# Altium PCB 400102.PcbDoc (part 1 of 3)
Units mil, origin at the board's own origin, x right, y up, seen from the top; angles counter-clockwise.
Board outline 3703.69 x 2381.89 mil, 2 copper layers (Top Layer, Bottom Layer), stack 61.8 mil thick; 220 components, 149 nets, 880 pads, 750 vias.
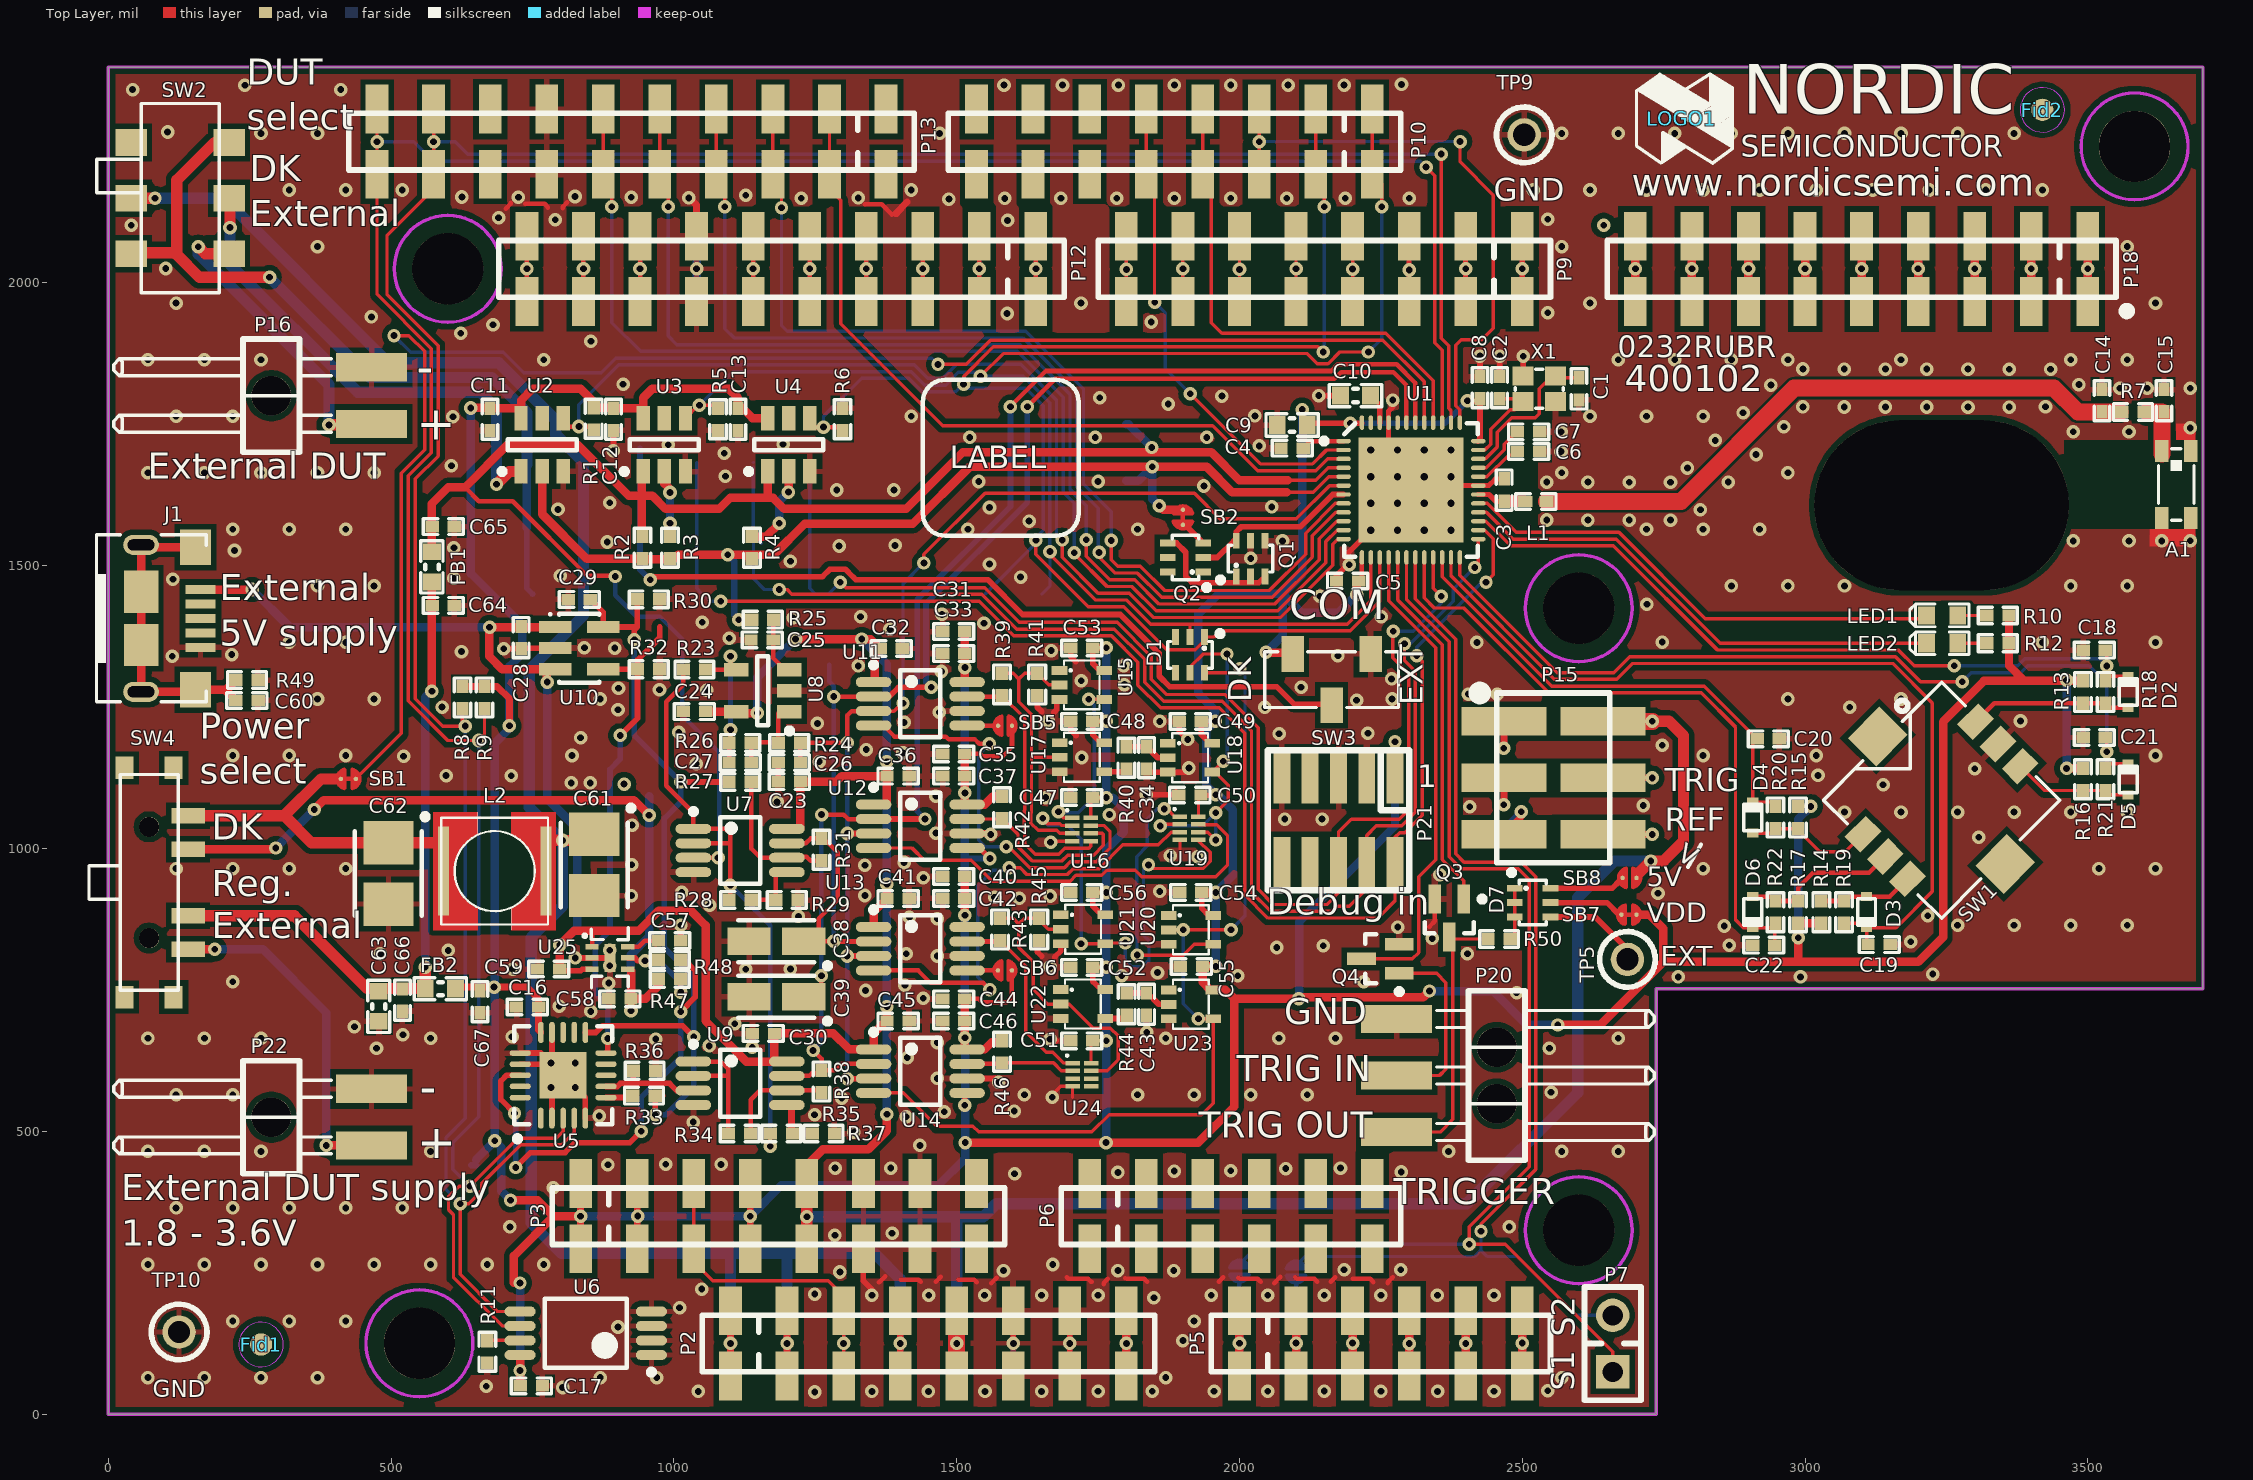
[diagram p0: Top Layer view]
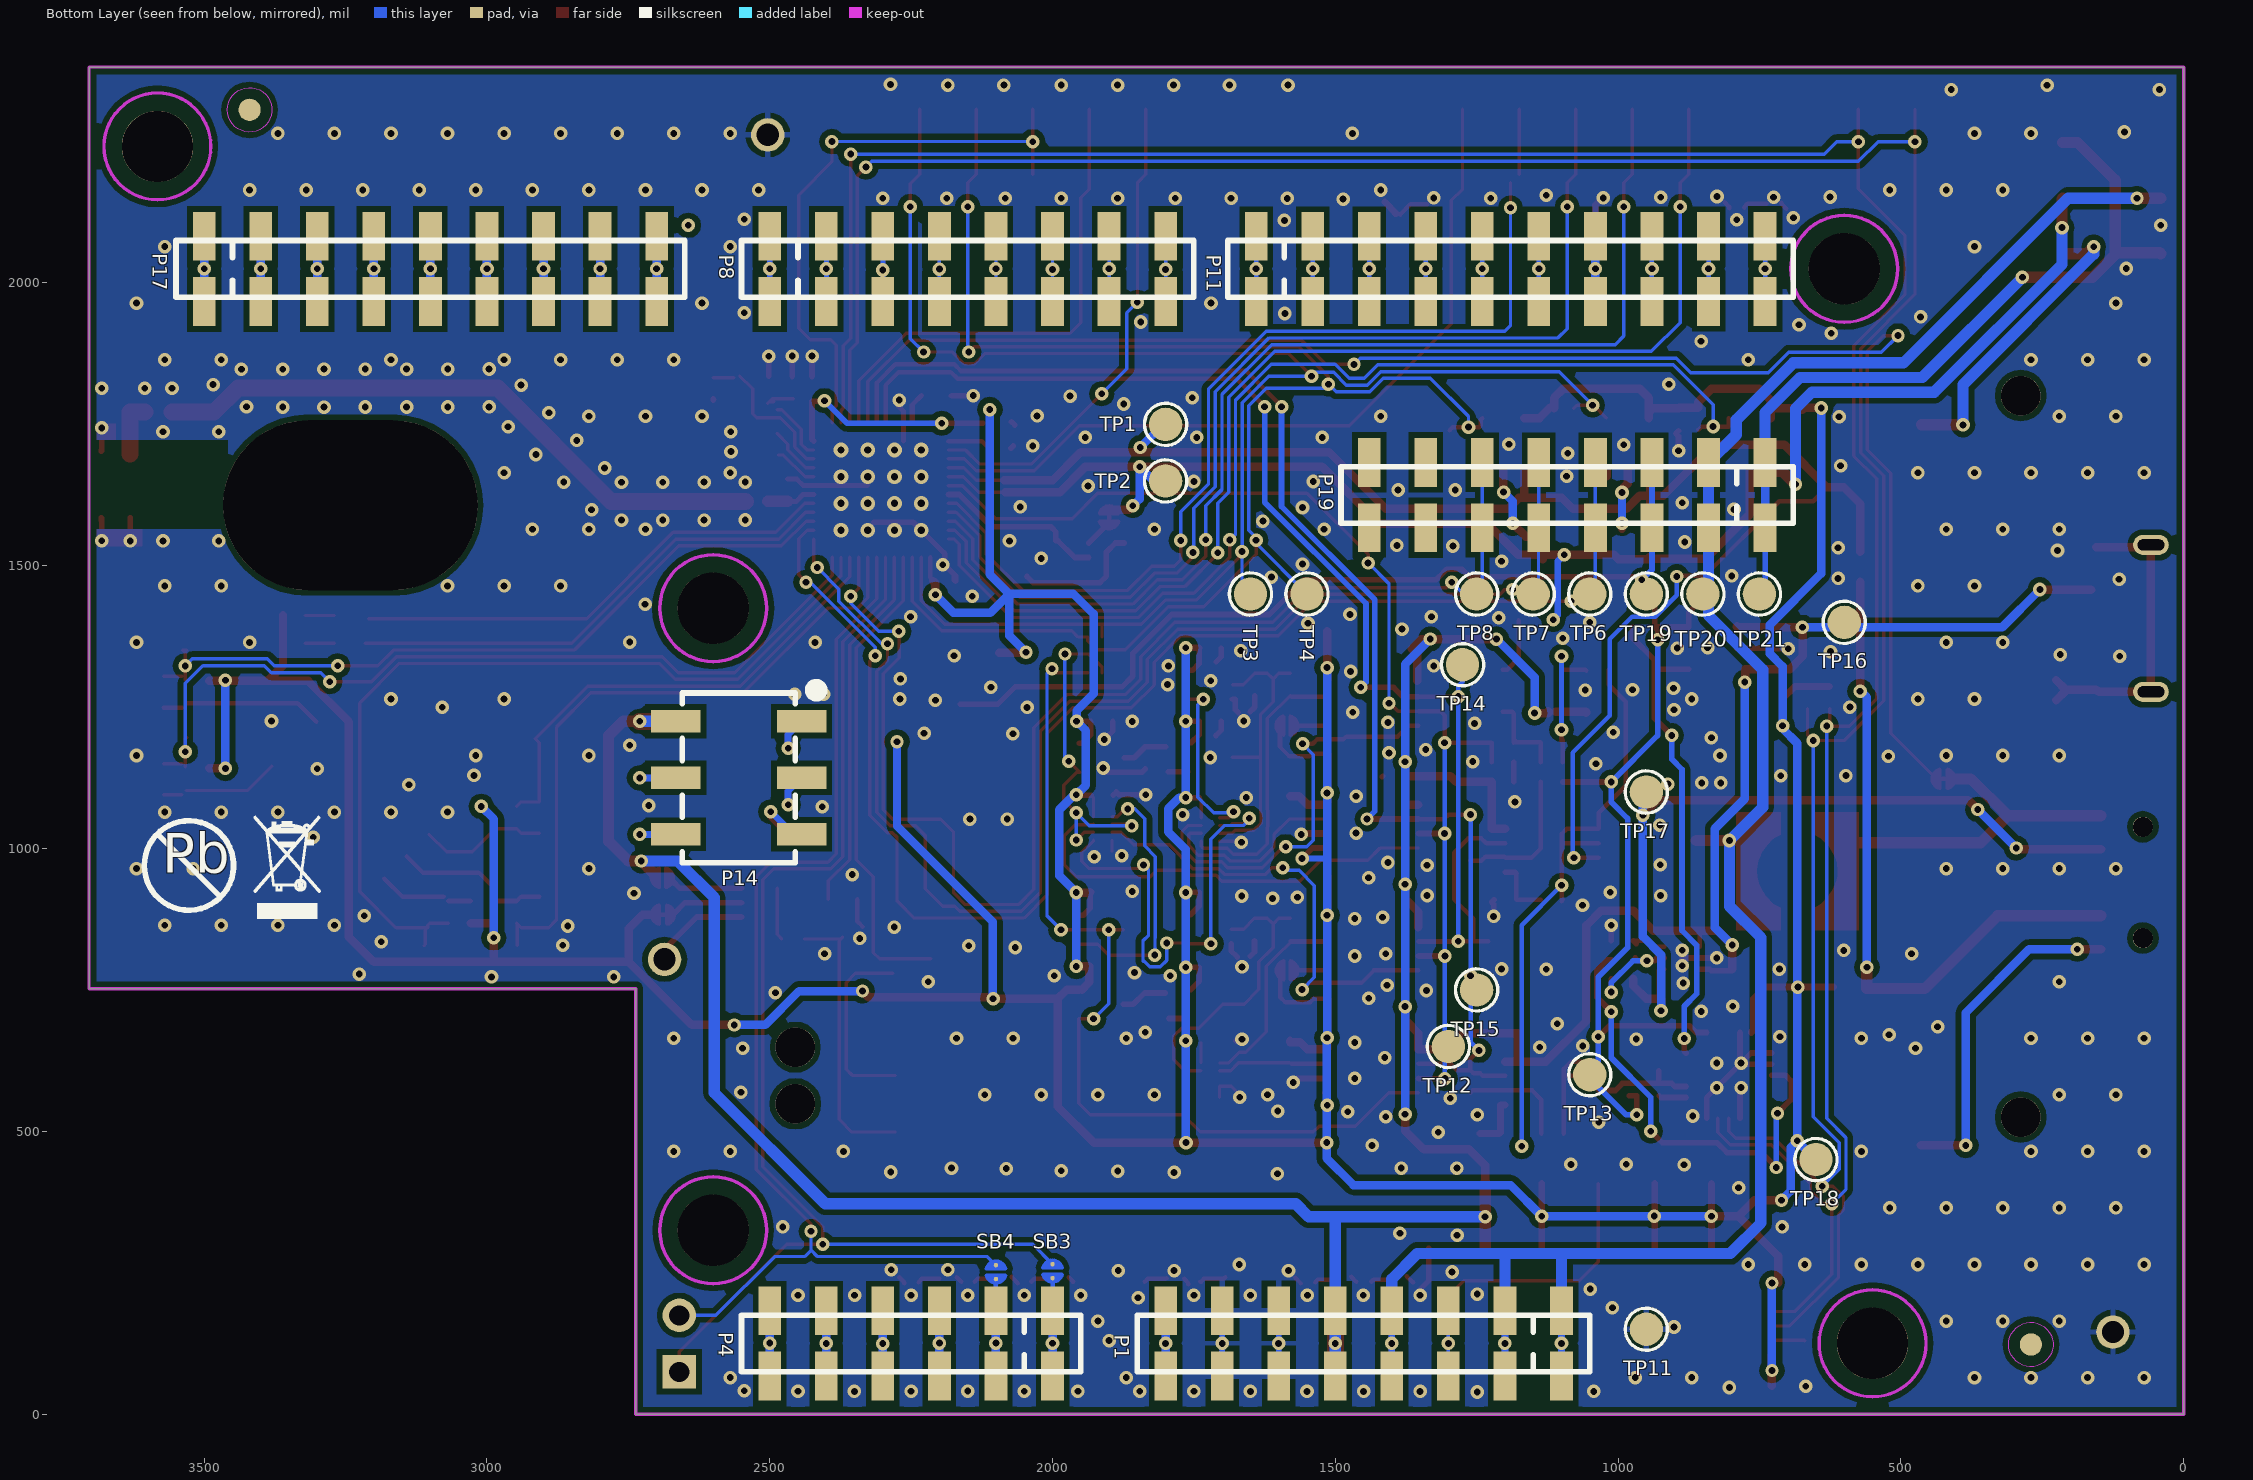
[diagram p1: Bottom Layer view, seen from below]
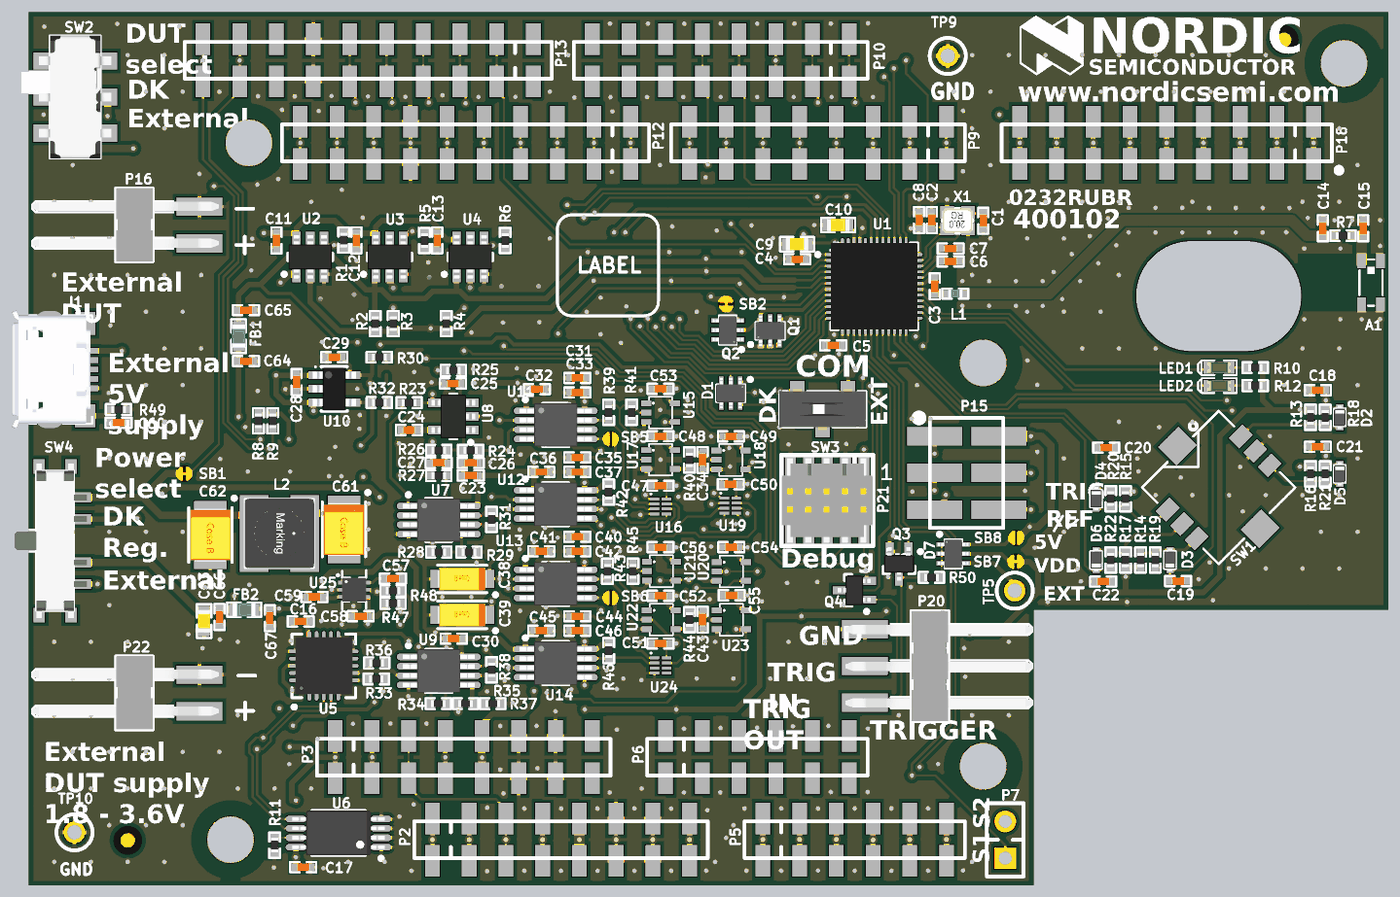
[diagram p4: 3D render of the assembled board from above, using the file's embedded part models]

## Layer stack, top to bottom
Top Solder: solder mask 0.4, Solder Resist, Dk 3.5
Top Layer: signal copper 1.4
Dielectric1: core 59, FR-4, Dk 4.4
Bottom Layer: signal copper 1.4
Bottom Solder: solder mask 0.4, Solder Resist, Dk 3.5

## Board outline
0,0 0,2381.89 3703.69,2381.89 3703.69,752.03 2736.92,752.03 2736.92,0

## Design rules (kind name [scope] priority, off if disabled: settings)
Clearance ANT_Clerance [InNet('ANT') or InNet('RF')] p1: gap=5
Clearance Polygon_Clearance [(InNamedPolygon('Top_Layer-GND')) or (InNamedPolygon('Bottom_Layer-GND'))] p2: gap=10
Clearance [All] p3: gap=5.91
ComponentClearance [All] p1 off: gap=10 collisioncheckmode=3 verticalgap=10 showdistances=FALSE
DiffPairsRouting [All] p1: maxlimit=5.91 minlimit=5.91 mostfreqgap=5.91 toplayer_minwidth=8 toplayer_maxwidth=15 toplayer_prefwidth=15 bottomlayer_minwidth=8 bottomlayer_maxwidth=15 bottomlayer_prefwidth=15 maxuncoupledlength=500
FabricationTestPointUsage TestPointUsage [All] p1: valid=0 allowmultiple=FALSE
FabricationTestpoint Testpoint [All] p1: side=3 testpointundercomponent=TRUE minsize=40 maxsize=100 preferedsize=60 minholesize=0 maxholesize=40 preferedholesize=32 testpointgrid=1 allowsidetop=TRUE allowsidebottom=TRUE usegrid=TRUE gridtolerance=0.01
Height [All] p1 off: minheight=0 maxheight=1000 prefheight=500
HoleSize [All] p1: absolutevalues=TRUE maxlimit=11196.85 minlimit=11.81 maxpercent=80.000 minpercent=20.000
MinimumAnnularRing [All] p1 off: minimumring=6
PolygonConnect PolygonConnect_1 [isVia and innet(gnd) or HasFootprint('COAXIAL-SWF')] p1: connectstyle=Direct reliefconductorwidth=10 reliefentries=4 polygonreliefangle="90 Angle" airgapwidth=10
PolygonConnect [All] p2: connectstyle=Relief reliefconductorwidth=10 reliefentries=4 polygonreliefangle="90 Angle" airgapwidth=10
RoutingVias [All] p1: holewidth=12 width=24 viastyle="Through Hole" minholewidth=11.81 minwidth=23.62 maxholewidth=28 maxwidth=50
SilkToSolderMaskClearance SilkscreenOverComponentPads [IsPad] p1: minsilkscreentomaskgap=10 clearancetoexposedcopper=TRUE
SolderMaskExpansion [All] p1: expansion=3
Width [All] p1: maxlimit=100 minlimit=6 preferedwidth=6
23 further rules are at their usual default settings.

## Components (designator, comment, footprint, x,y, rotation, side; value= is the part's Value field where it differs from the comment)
A1 "2450AT18D0100" 2450AT18D0100_STD 3656.42,1643.7 r270 top
C1 "12pF" CAPC1005X04L 2600.15,1812.69 r270 top
C2 "12pF" CAPC1005X04L 2460.15,1814.86 r90 top
C3 "0.8pF" CAPC1005X04L 2468.15,1633.86 r270 top
C4 "100nF" CAPC1005X04L 2093.15,1707.86 r180 top
C5 "100nF" CAPC1005X04L 2191.15,1472.86 r180 top
C6 "N.C." CAPC1005X04L 2511.15,1701.86 r180 top
C7 "100pF" CAPC1005X04L 2511.15,1736.86 r0 top
C8 "100nF" CAPC1005X04L 2425.15,1814.86 r90 top
C9 "4.7µF" CAPC1608X06L 2093.15,1748.86 r180 top
C10 "1.0µF" CAPC1608X06L 2205.15,1800.86 r0 top
C11 "100nF" CAPC1005X04L 675,1758.98 r270 top
C12 "100nF" CAPC1005X04L 893,1758.98 r270 top
C13 "100nF" CAPC1005X04L 1113,1758.98 r270 top
C14 "N.C." CAPC1005X04L 3525,1791.98 r270 top
C15 "N.C." CAPC1005X04L 3635,1791.98 r270 top
C16 "100nF" CAPC1005X04L 741,720 r0 top
C17 "100nF" CAPC1005X04L 748,50 r0 top
C18 "1.0µF" CAPC1005X04L 3511.42,1350.72 r180 top
C19 "1.0µF" CAPC1005X04L 3131,830 r0 top
C20 "1.0µF" CAPC1005X04L 2935,1194 r0 top
C21 "1.0µF" CAPC1005X04L 3511.42,1196.35 r180 top
C22 "1.0µF" CAPC1005X04L 2927,829 r180 top
C23 "100nF" CAPC1005X04L 1204.24,1118.1 r0 top
C24 "100nF" CAPC1005X04L 1036.23,1242 r0 top
C25 "2.2pF" CAPC1005X04L 1156,1369 r0 top
C26 "220pF" CAPC1005X04L 1204,1152.3 r0 top
C27 "2.2pF" CAPC1005X04L 1117.08,1152.36 r180 top
C28 "4.7µF" CAPC1005X04L 729.95,1373 r90 top
C29 "1.0µF" CAPC1005X04L 832.49,1440.66 r0 top
C30 "100nF" CAPC1005X04L 1158,673.2 r0 top
C31 "2.2µF" CAPC1005X04L 1494.71,1383.83 r0 top
C32 "100nF" CAPC1005X04L 1384.28,1353.46 r0 top
C33 "100nF" CAPC1005X04L 1494.71,1344.46 r0 top
C34 "1.0nF" CAPC1005X04L 1835.91,1160.37 r90 top
C35 "2.2µF" CAPC1005X04L 1494.71,1167.3 r0 top
C36 "100nF" CAPC1005X04L 1396.28,1127.93 r0 top
C37 "100nF" CAPC1005X04L 1494.71,1127.93 r0 top
C38 "47µF" CAPMP3216X18N 1181,836 r180 top
C39 "47µF" CAPMP3216X18N 1181,738 r180 top
C40 "2.2µF" CAPC1005X04L 1494.7,950.76 r0 top
C41 "100nF" CAPC1005X04L 1396.28,911.39 r0 top
C42 "100nF" CAPC1005X04L 1494.7,911.39 r0 top
C43 "1.0nF" CAPC1005X04L 1835.88,724.9 r90 top
C44 "2.2µF" CAPC1005X04L 1494.7,734.23 r0 top
C45 "100nF" CAPC1005X04L 1396.28,694.86 r0 top
C46 "100nF" CAPC1005X04L 1494.7,694.86 r0 top
C47 "100nF" CAPC1005X04L 1721.15,1090 r0 top
C48 "100nF" CAPC1005X04L 1721.15,1225 r0 top
C49 "100nF" CAPC1005X04L 1912.91,1224.74 r0 top
C50 "100nF" CAPC1005X04L 1912.36,1094.38 r0 top
C51 "100nF" CAPC1005X04L 1721.15,660 r0 top
C52 "100nF" CAPC1005X04L 1721.15,790 r0 top
C53 "100nF" CAPC1005X04L 1721.15,1354.37 r0 top
C54 "100nF" CAPC1005X04L 1913.75,922.62 r0 top
C55 "100nF" CAPC1005X04L 1915,791.49 r0 top
C56 "100nF" CAPC1005X04L 1721.15,922.5 r0 top
C57 "100nF" CAPC1005X04L 992.45,836.95 r180 top
C58 "1.0µF" CAPC1005X04L 904.45,734.33 r180 top
C59 "1.0µF" CAPC1005X04L 778.45,786.83 r180 top
C60 "100nF" CAPC1005X04L 245,1262 r0 top
C61 "330µF" CAPMP3528X21N 859,971 r270 top
C62 "330µF" CAPMP3528X21N 495,955.82 r270 top
C63 "10µF" CAPC1608X06L 478,721 r90 top
C64 "100nF" CAPC1005X04L 592,1430 r180 top
C65 "1.0µF" CAPC1005X04L 592,1569 r180 top
C66 "100nF" CAPC1005X04L 520,732 r90 top
C67 "1.0µF" CAPC1005X04L 657,729 r90 top
D1 "SD103ATW-7-F" SOT-363 1938,1374 r180 top
D2 "1PS79SB30.115" SOD-523 3571.42,1276.74 r270 top
D3 "1PS79SB30.115" SOD-523 3108.82,887.52 r90 top
D4 "1PS79SB30.115" SOD-523 2907.64,1054.8 r270 top
D5 "1PS79SB30.115" SOD-523 3571.42,1122.38 r270 top
D6 "1PS79SB30.115" SOD-523 2907.64,887.52 r90 top
D7 "SD103ATW-7-F" SOT-363 2487,930 r270 top
FB1 "1k/0.8A" INDC1608X06L 572,1498 r90 top
FB2 "1k/0.8A" INDC1608X06L 587,752 r0 top
Fid1 "Fiducial mark" Fiducial 270,123 r0 top
Fid2 "Fiducial mark" Fiducial 3419.75,2306.2 r0 top
J1 "MicroUSB-B" USB-Micro-B-RA-SMD-PiP 163,1406.97 r0 top
L1 "3.9nH" INDC1005X04L 2524.15,1613.86 r0 top
L2 "220µH" WE-TPC_4848 683,960 r270 top
LED1 "L0603G" LED_0603_G 3242.58,1412.13 r0 top
LED2 "L0603G" LED_0603_G 3242.58,1362.95 r0 top
LOGO1 "Nordic Logo M" NORDIC_LOGO_M 2782,2290 r0 top
P1 "Pin List 1x8" LIST_1x8_SMD 1100,125 r0 bottom locked
P2 "Socket 1x8" SOCKET_1x8_SMD 1100,125 r0 top
P3 "Socket 1x8" SOCKET_1x8_SMD 835,349.84 r0 top
P4 "Pin List 1x6" LIST_1x6_SMD 2000,125 r0 bottom locked
P5 "Socket 1x6" SOCKET_1x6_SMD 2000,125 r0 top
P6 "Socket 1x6" SOCKET_1x6_SMD 1735,349.84 r0 top
P7 "Pin List 1x2" LIST_1x2 2660,124.68 r90 top
P8 "Pin List 1x8" LIST_1x8_SMD 2500,2025 r180 bottom locked
P9 "Socket 1x8" SOCKET_1x8_SMD 2500,2025 r180 top
P10 "Socket 1x8" SOCKET_1x8_SMD 2235,2249.84 r180 top
P11 "Pin List 1x10" LIST_1x10_SMD 1640,2025 r180 bottom locked
P12 "Socket 1x10" SOCKET_1x10_SMD 1640,2025 r180 top locked
P13 "Socket 1x10" SOCKET_1x10_SMD 1375,2249.84 r180 top
P14 "Socket 2x3" SOCKET_2x3_SMD-2.54mm-bottom 2555,1125 r270 top locked
P15 "Pin Hdr 2x3" "Molex 15-91-2060" 2555,1125 r270 top locked
P16 "Pin List 1x2, Angled" LIST_ANG_1x2-SMD-2.54MM 465,1800.86 r270 top
P17 "Pin List 1x9" LIST_1x9_SMD 3500,2025 r180 bottom locked
P18 "Socket 1x9" SOCKET_1x9_SMD 3500,2025 r180 top
P19 "Socket 1x8" SOCKET_1x8_SMD 740,1625 r0 bottom
P20 "Pin List 1x3, Angled" LIST_ANG_1x3-SMD-2.54MM 2277.83,598.66 r90 top
P21 "Pin Header 2x5, 1.27mm" HDR_2x5-SMD-1.27mm-K 2175,1050 r180 top
P22 "Pin List 1x2, Angled" LIST_ANG_1x2-SMD-2.54MM 465,525 r270 top
Q1 "DMMT3904W" SOT-363 1994,1481 r0 top
Q2 "DMMT3904W" SOT-363 1936,1489 r90 top
Q3 "BSS138" SOT65P210X110-3N 2371,877 r270 top
Q4 "BSS138" SOT65P210X110-3N 2249,805 r180 top
R1 "47k" RESC1005X04L 858,1759.77 r90 top
R2 "510R" RESC1005X04L 944.31,1532 r270 top
R3 "33R" RESC1005X04L 993,1532 r270 top
R4 "1R8" RESC1005X04L 1137.75,1532 r270 top
R5 "47k" RESC1005X04L 1078,1758.98 r90 top
R6 "47k" RESC1005X04L 1298,1758.98 r90 top
R7 "0R" RESC1005X04L 3580,1771.95 r0 top
R8 "4k7" RESC1005X04L 626,1267 r90 top
R9 "4k7" RESC1005X04L 665,1267 r90 top
R10 "220R" RESC1005X04L 3341.01,1412.13 r0 top
R11 "47k" RESC1005X04L 670,110 r90 top
R12 "220R" RESC1005X04L 3341.01,1362.95 r0 top
R13 "100k" RESC1005X04L 3491.42,1276.74 r90 top
R14 "100k" RESC1005X04L 3028.82,887.52 r270 top
R15 "100k" RESC1005X04L 2987.64,1054.8 r90 top
R16 "100k" RESC1005X04L 3491.42,1122.38 r90 top
R17 "100k" RESC1005X04L 2987.64,887.52 r270 top
R18 "18k" RESC1005X04L 3531.42,1276.74 r90 top
R19 "18k" RESC1005X04L 3068.82,887.52 r270 top
R20 "18k" RESC1005X04L 2947.64,1054.8 r90 top
R21 "18k" RESC1005X04L 3531.42,1122.38 r90 top
R22 "18k" RESC1005X04L 2947.64,887.52 r270 top
R23 "1k" RESC1005X04L 1036.23,1316.4 r0 top
R24 "100R" RESC1005X04L 1204,1186.89 r0 top
R25 "10R" RESC1005X04L 1157,1404.64 r0 top
R26 "10k" RESC1005X04L 1117,1186.89 r0 top
R27 "10k" RESC1005X04L 1117.08,1117.75 r0 top
R28 "10k" RESC1005X04L 1117.08,909.25 r180 top
R29 "10k" RESC1005X04L 1199.55,909.25 r180 top
R30 "1k" RESC1005X04L 955.13,1440.66 r180 top
R31 "10k" RESC1005X04L 1261,998.08 r90 top
R32 "27k" RESC1005X04L 955.13,1317 r180 top
R33 "30k" RESC1005X04L 947,563 r0 top
R34 "10k" RESC1005X04L 1116,496 r0 top
R35 "10k" RESC1005X04L 1190,496 r180 top
R36 "2k0" RESC1005X04L 948,607 r180 top
R37 "10k" RESC1005X04L 1264.42,496 r180 top
R38 "10k" RESC1005X04L 1261,588 r90 top
R39 "1k" RESC1005X04L 1579.77,1290.12 r90 top
R40 "100R" RESC1005X04L 1800,1160.37 r90 top
R41 "1k" RESC1005X04L 1642.41,1290.1 r90 top
R42 "1k" RESC1005X04L 1580.07,1072.81 r90 top
R43 "1k" RESC1005X04L 1576.77,856.85 r90 top
R44 "100R" RESC1005X04L 1800.44,724.9 r90 top
R45 "1k" RESC1005X04L 1645.97,856.85 r90 top
R46 "1k" RESC1005X04L 1580.07,640.56 r90 top
R47 "62k" RESC1005X04L 992.45,769.33 r180 top
R48 "33k" RESC1005X04L 992.45,803.52 r180 top
R49 "10k" RESC1005X04L 245,1298 r0 top
R50 "1k" RESC1005X04L 2459,840 r0 top
SB1 "Solderbridge" Solderbridge_Shorted 411,1123 r0 top net-tie
SB2 "Solderbridge" Solderbridge_Shorted 1900,1599 r270 top net-tie
SB3 "Solderbridge" Solderbridge#1 2000,265 r270 bottom
SB4 "Solderbridge" Solderbridge#1 2100,263.36 r270 bottom
SB5 "Solderbridge" Solderbridge#1 1597.77,1217.12 r180 top
SB6 "Solderbridge" Solderbridge#1 1597.46,784.42 r180 top
SB7 "Solderbridge" Solderbridge_Shorted 2702,883 r180 top net-tie
SB8 "Solderbridge" Solderbridge#2 2702,948 r180 top
SW1 "Multi-directional SW" ALPS_SKRHAAE010 3241.48,1085.44 r45 top
SW2 "CL-SB-22B-11T" CL-SB-22B-1x 127,2150 r270 top locked
SW3 "Switch" CJS-120xA 2163,1298.67 r180 top
SW4 "CUS-13TB" CUS-13B 72,940 r270 top
TP1 "Ø1.5mm,SMD" TP_SMD_Ø1.5mm 1800,1750 r180 bottom
TP2 "Ø1.5mm,SMD" TP_SMD_Ø1.5mm 1800,1650 r180 bottom
TP3 "Ø1.5mm,SMD" TP_SMD_Ø1.5mm 1650,1450 r180 bottom
TP4 "Ø1.5mm,SMD" TP_SMD_Ø1.5mm 1550,1450 r180 bottom
TP5 "TP" TEST_POINT_5000 2686,804 r0 top
TP6 "Ø1.5mm,SMD" TP_SMD_Ø1.5mm 1050,1450 r180 bottom
TP7 "Ø1.5mm,SMD" TP_SMD_Ø1.5mm 1150,1450 r180 bottom
TP8 "Ø1.5mm,SMD" TP_SMD_Ø1.5mm 1250,1450 r180 bottom
TP9 "TP" TEST_POINT_5001 2503.46,2262.02 r0 top
TP10 "TP" TEST_POINT_5001 125,145 r0 top
TP11 "Ø1.0mm,SMD" TP_SMD_Ø1.5MM 950,150 r180 bottom
TP12 "Ø1.5mm,SMD" TP_SMD_Ø1.5mm 1300,650 r180 bottom
TP13 "Ø1.5mm,SMD" TP_SMD_Ø1.5mm 1050,600 r180 bottom
TP14 "Ø1.5mm,SMD" TP_SMD_Ø1.5mm 1275,1325 r180 bottom
TP15 "Ø1.5mm,SMD" TP_SMD_Ø1.5mm 1250,750 r180 bottom
TP16 "Ø1.5mm,SMD" TP_SMD_Ø1.5mm 600,1400 r180 bottom
TP17 "Ø1.5mm,SMD" TP_SMD_Ø1.5mm 950,1100 r180 bottom
TP18 "Ø1.5mm,SMD" TP_SMD_Ø1.5mm 650,450 r180 bottom
TP19 "Ø1.5mm,SMD" TP_SMD_Ø1.5mm 950,1450 r180 bottom
TP20 "Ø1.5mm,SMD" TP_SMD_Ø1.5mm 850,1450 r180 bottom
TP21 "Ø1.5mm,SMD" TP_SMD_Ø1.5mm 750,1450 r180 bottom
U1 "nRF52832-QFAA" QFN40P600X600X90-48N 2303.15,1633.86 r0 top locked
U2 "ADG801BRTZ-500RL7" SOT95P280X145-6N 767,1713.98 r90 top
U3 "ADG801BRTZ-500RL7" SOT95P280X145-6N 983,1713.98 r90 top
U4 "ADG801BRTZ-500RL7" SOT95P280X145-6N 1203,1713.98 r90 top
U5 "MCP4451_100k" QFN50P400X400X80_HS-21N 804,599 r90 top
U6 "M24C02" TSOP65P640X120-8N 844,143 r180 top
U7 "TLV272" MSOP65P490X110-8N 1117,996.5 r0 top
U8 "AD8615" SOT95P280X145-5N 1157,1279 r180 top
U9 "TLV272" MSOP65P490X110-8N 1117,585 r0 top
U10 "MCP1824T-ADJE/OT" SOT-23-5 832.49,1354.37 r270 top
U11 "LTC6752-2" MSOP65P490X110-8N 1435.65,1255.88 r0 top
U12 "LTC6752-2" MSOP65P490X110-8N 1435.65,1039.34 r0 top
U13 "LTC6752-2" MSOP65P490X110-8N 1435.65,822.81 r0 top
U14 "LTC6752-2" MSOP65P490X110-8N 1435.65,606.27 r0 top
U15 "74LVC1GU04" SOT-353 1681.78,1315 r270 top
U16 "74LVC2G08" PSON35P100X50-8N 1721,1033.76 r0 top
U17 "74LVC1G17" SOT-353 1682,1187 r270 top
U18 "74LVC1G17" SOT-353 1873.41,1186.16 r270 top
U19 "74LVC2G08" PSON35P100X50-8N 1911.1,1035.83 r0 top
U20 "74LVC1GU04" SOT-353 1874.62,881.86 r270 top
U21 "74LVC1GU04" SOT-353 1684.18,882.88 r270 top
U22 "74LVC1G17" SOT-353 1683.75,750.49 r270 top
U23 "74LVC1G17" SOT-353 1874.62,750.13 r270 top
U24 "74LVC2G08" PSON35P100X50-8N 1721.15,600 r0 top
U25 "MIC5353YMT-ADJ" QFN50P160X160X60_6N 886.62,806.52 r0 top
X1 "32MHz" BT-XTAL_2016 2530.15,1812.86 r180 top

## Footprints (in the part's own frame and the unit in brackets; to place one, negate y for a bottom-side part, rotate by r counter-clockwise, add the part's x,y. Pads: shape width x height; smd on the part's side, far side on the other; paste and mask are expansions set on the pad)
2450AT18D0100_STD [mm] "2450MHz Antenna"
  rect 1x0.6 smd mask+0.051: 1(-1.5,-0.65) 2(-1.5,0.65) 2(1.5,0.65) 2(1.5,-0.65)
  Top Layer pour cut-out: -2,-5.05 -2,0.95 2,0.95 2,-5.05
  Bottom Layer pour cut-out: -2,-5.05 -2,0.95 2,0.95 2,-5.05
  silkscreen extent -1.6,-0.8 1.6,0.8, body extent -1.61,-0.81 1.61,0.81, height 1.2
ALPS_SKRHAAE010 [mm] "Joyswitch, 5-way,  7.5x7.5x2.14 mm"
  rect 2x1.8 smd: 0(0,4.05) 0(0,-4.05)
  rect 1.35x1 smd: 1(-3.575,1.415) 2(-3.575,0) 3(-3.575,-1.415) 4(3.575,1.415) 5(3.575,0) 6(3.575,-1.415)
  silkscreen extent -3.75,-3.75 3.75,4.5
BT-XTAL_2016 [mm] "Crystal 2.0 x 1.6 mm"
  rect 0.95x0.85 smd: 1(-0.725,-0.575) 2(0.725,-0.575) 3(0.725,0.575) 4(-0.725,0.575)
  silkscreen extent -1.08,-0.88 1.08,0.88, body extent -1.05,-0.85 1.05,0.85, height 0.56
CAPC1005X04L [mm] "Chip Capacitor, 2-Leads, Body 1.0x0.5mm, IPC High Density"
  rect 0.6x0.5 smd: 1(-0.5,0) 2(0.5,0)
  silkscreen extent -0.9,-0.35 0.9,0.35, body extent -0.51,-0.25 0.51,0.25, height 0.5
CAPC1608X06L [mm] "Chip Capacitor, 2-Leads, Body 1.6x0.8mm, IPC High Density"
  rect 0.75x0.8 smd: 1(-0.675,0) 2(0.675,0)
  silkscreen extent -1.17,-0.5 1.17,0.5, body extent -0.8,-0.43 0.8,0.43, height 0.8
CAPMP3216X18N [mm] "Molded Capacitor, 2-Leads, Body 3.20x1.60mm, IPC Medium Density"
  rect 1.95x1.25 smd: 1(-1.225,0) 2(1.225,0)
  silkscreen extent -2.43,-0.95 1.7,1.22, body extent -1.7,-0.8 1.7,0.8, height 1.64
CAPMP3528X21N [mm] "Molded Capacitor, 2-Leads, Body 3.5x2.8mm, IPC Medium Density"
  rect 1.95x2.25 smd: 1(-1.375,0) 2(1.375,0)
  silkscreen extent -2.67,-1.5 1.9,1.78, body extent -1.84,-1.41 1.85,1.41, height 2.09
CJS-120xA [mm] "Slide Switches - SPDT, SMD, ON-ON"
  rect 1x1.6 smd: 1(1.75,-1.15) 2(0,1.15) 3(-1.75,-1.15)
  silkscreen extent -3,-1.25 3,1.25, body extent -3,-1.4 3,1.45, height 2.5
CL-SB-22B-1x [mm] "Slide Switches - DPDT, SMD, ON-ON"
  rect 1.2x1.4 smd: 1(2.5,-2.2) 2(0,-2.2) 3(-2.5,-2.2) 4(2.5,2.2) 5(0,2.2) 6(-2.5,2.2)
  silkscreen extent -4.25,-3.75 4.25,1.75, body extent -4.25,-3.75 4.25,2.5, height 3.5
CUS-13B [mm] "Slide Switches - SP3T, SMD, ON-ON-ON"
  rect 1x0.8 smd: 0(-5.15,-1.1) 0(-5.15,1.1) 0(5.15,-1.1) 0(5.15,1.1)
  round 0.9 hole 0.9: 0(-2.5,0) 0(2.5,0)
  rect 0.7x1.5 smd: 1(-3,1.75) 2(-1.5,1.75) 3(1.5,1.75) 4(3,1.75)
  silkscreen extent -4.85,-2.7 4.85,1.3, body extent -5.35,-2.8 5.35,2.2, height 1.4
Fiducial [mm] "Fiducial Mark"
  round 1 smd paste-10 mask+0.5: 0(0,0)
  round 1 smd far side paste-10 mask+0.5: 0(0,0)
  Keep-Out Layer circle w0.01: c0,0 r1
HDR_2x5-SMD-1.27mm-K [mm] "SMT MICRO HEADER, (1,27) .050\" Keying Shroud"
  rect 0.76x2.4 smd: 1(-2.54,-1.95) 2(-2.54,1.95) 3(-1.27,-1.95) 4(-1.27,1.95) 5(0,-1.95) 6(0,1.95) 7(1.27,-1.95) 8(1.27,1.95) 9(2.54,-1.95) 10(2.54,1.95)
  silkscreen extent -3.18,-3.15 3.18,3.15, body extent -3.14,-2.92 3.14,2.92, height 6.11
INDC1005X04L [mm] "Chip Inductor, 2-Leads, Body 1.0x0.5mm, IPC High Density"
  rect 0.65x0.5 smd: 1(-0.475,0) 2(0.475,0)
  silkscreen extent -0.9,-0.35 0.9,0.35, body extent -0.5,-0.3 0.5,0.3, height 0.5
INDC1608X06L [mm] "Chip Inductor, 2-Leads, Body 1.6x0.8mm, IPC High Density"
  rect 0.75x0.8 smd: 1(-0.675,0) 2(0.675,0)
  silkscreen extent -1.17,-0.5 1.17,0.5, body extent -0.8,-0.48 0.8,0.48, height 0.8
LED_0603_G [mil] "SMD Super Bright LED, GREEN"
  rect 30x32 smd: 1(-27.5,0) 2(27.5,0)
  silkscreen extent -58,-20 48,20, body extent -32,-16 32,16, height 24
LIST_1x2 [mm] "Pin List, 2.54mm through hole"
  rect 1.5x1.5 hole 0.9: 1(-1.27,0)
  round 1.5 hole 0.9: 2(1.27,0)
  silkscreen extent -2.54,-1.27 2.54,1.27
LIST_1x6_SMD [mm] "Pin List, 2.54mm, SMD"
  rect 1.02x2.19 smd: 1(0,-1.465) 1(0,1.465) 2(2.54,-1.465) 2(2.54,1.465) 3(5.08,-1.465) 3(5.08,1.465) 4(7.62,-1.465) 4(7.62,1.465) 5(10.16,-1.465) 5(10.16,1.465) 6(12.7,-1.465) 6(12.7,1.465)
  silkscreen extent -1.27,-1.27 13.97,1.27, body extent -1.27,-2.5 13.97,2.5, height 9.82
LIST_1x8_SMD [mm] "Pin List, 2.54mm, SMD"
  rect 1.02x2.19 smd: 1(0,-1.465) 1(0,1.465) 2(2.54,-1.465) 2(2.54,1.465) 3(5.08,-1.465) 3(5.08,1.465) 4(7.62,-1.465) 4(7.62,1.465) 5(10.16,-1.465) 5(10.16,1.465) 6(12.7,-1.465) 6(12.7,1.465) 7(15.24,-1.465) 7(15.24,1.465) 8(17.78,-1.465) 8(17.78,1.465)
  silkscreen extent -1.27,-1.27 19.05,1.27, body extent -1.27,-2.5 19.05,2.5, height 9.82
LIST_1x9_SMD [mm] "Pin List, 2.54mm, SMD"
  rect 1.02x2.19 smd: 1(0,-1.465) 1(0,1.465) 2(2.54,-1.465) 2(2.54,1.465) 3(5.08,-1.465) 3(5.08,1.465) 4(7.62,-1.465) 4(7.62,1.465) 5(10.16,-1.465) 5(10.16,1.465) 6(12.7,-1.465) 6(12.7,1.465) 7(15.24,-1.465) 7(15.24,1.465) 8(17.78,-1.465) 8(17.78,1.465) 9(20.32,-1.465) 9(20.32,1.465)
  silkscreen extent -1.27,-1.27 21.59,1.27
LIST_1x10_SMD [mm] "Pin List, 2.54mm, SMD"
  rect 1.02x2.19 smd: 1(0,-1.465) 1(0,1.465) 2(2.54,-1.465) 2(2.54,1.465) 3(5.08,-1.465) 3(5.08,1.465) 4(7.62,-1.465) 4(7.62,1.465) 5(10.16,-1.465) 5(10.16,1.465) 6(12.7,-1.465) 6(12.7,1.465) 7(15.24,-1.465) 7(15.24,1.465) 8(17.78,-1.465) 8(17.78,1.465) 9(20.32,-1.465) 9(20.32,1.465) 10(22.86,-1.465) 10(22.86,1.465)
  silkscreen extent -1.27,-1.27 24.13,1.27
LIST_ANG_1x2-SMD-2.54MM [mm] "Pin List, 2.54mm, Surface Mount, Angled"
  round 1.78 hole 1.78: 0(0,-4.496)
  rect 1.27x3.18 smd: 1(-1.27,0) 2(1.27,0)
  silkscreen extent -2.54,-11.58 2.54,-1.8, body extent -2.56,-11.61 2.52,1.35, height 3.03
LIST_ANG_1x3-SMD-2.54MM [mm] "Pin List, 2.54mm, Surface Mount, Angled"
  round 1.78 hole 1.78: 0(-1.27,-4.496) 0(1.27,-4.496)
  rect 1.27x3.18 smd: 1(-2.54,0) 2(0,0) 3(2.54,0)
  silkscreen extent -3.81,-11.58 3.81,-1.8, body extent -3.83,-11.61 3.79,1.35, height 3.03
"Molex 15-91-2060" [mil] "MOLEX - 15-91-2060 - BOARD-BOARD CONN, HEADER, 6WAY, 2ROW"
  rect 50x150 smd: 1(-100,-87.5) 2(-100,87.5) 3(0,-87.5) 4(0,87.5) 5(100,-87.5) 6(100,87.5)
  silkscreen extent -160,-140 150,100
MSOP65P490X110-8N [mm] "MSOP, 8-Leads, Body 3,0x3,0mm (max), Pitch 0,65mm, IPC Medium Density"
  oval 1.6x0.45 smd: 1(-2.1,0.975) 2(-2.1,0.325) 3(-2.1,-0.325) 4(-2.1,-0.975) 5(2.1,-0.975) 6(2.1,-0.325) 7(2.1,0.325) 8(2.1,0.975)
  silkscreen extent -2.22,-1.5 0.9,1.87, body extent -2.5,-1.5 2.5,1.5, height 0.92
NORDIC_LOGO_M [mil] "Medium Nordic Logo"
  silkscreen extent -80,-78 90,80
PSON35P100X50-8N [mm] "PSON, 8-Leads, Body 1,35x1,00mm, Pitch 0,35mm, IPC Medium Density"
  rect 0.65x0.2 smd: 1(-0.415,0.525) 2(-0.415,0.175) 3(-0.415,-0.175) 4(-0.415,-0.525) 5(0.415,-0.525) 6(0.415,-0.175) 7(0.415,0.175) 8(0.415,0.525)
  silkscreen extent -0.71,0.81 -0.61,0.91, body extent -0.53,-0.7 0.53,0.7, height 0.5
QFN40P600X600X90-48N [mm] "QFN, 48-Leads, Body 6,0x6,0mm (max), Pitch 0,40mm, IPC Medium Density"
  oval 0.65x0.2 smd: 1(-3.025,2.2) 2(-3.025,1.8) 3(-3.025,1.4) 4(-3.025,1) 5(-3.025,0.6) 6(-3.025,0.2) 7(-3.025,-0.2) 8(-3.025,-0.6) 9(-3.025,-1) 10(-3.025,-1.4) 11(-3.025,-1.8) 12(-3.025,-2.2) 25(3.025,-2.2) 26(3.025,-1.8) 27(3.025,-1.4) 28(3.025,-1) 29(3.025,-0.6) 30(3.025,-0.2) 31(3.025,0.2) 32(3.025,0.6) 33(3.025,1) 34(3.025,1.4) 35(3.025,1.8) 36(3.025,2.2)
  oval 0.2x0.65 smd: 13(-2.2,-3.025) 14(-1.8,-3.025) 15(-1.4,-3.025) 16(-1,-3.025) 17(-0.6,-3.025) 18(-0.2,-3.025) 19(0.2,-3.025) 20(0.6,-3.025) 21(1,-3.025) 22(1.4,-3.025) 23(1.8,-3.025) 24(2.2,-3.025) 37(2.2,3.025) 38(1.8,3.025) 39(1.4,3.025) 40(1,3.025) 41(0.6,3.025) 42(0.2,3.025) 43(-0.2,3.025) 44(-0.6,3.025) 45(-1,3.025) 46(-1.4,3.025) 47(-1.8,3.025) 48(-2.2,3.025)
  rect 4.7x4.7 smd: 49(0,0)
  silkscreen extent -4.02,-3 3,3, body extent -3.02,-3.02 3.02,3.02, height 0.86
QFN50P160X160X60_6N [mm] "QFN, 6-Leads, Body 1.60x1.60mm, Pitch 0.50mm, Thermal Pad 0.50x1.26mm, IPC Medium Density"
  rect 0.6x0.25 smd: 1(-0.8,0.5) 2(-0.8,0) 3(-0.8,-0.5) 4(0.8,-0.5) 5(0.8,0) 6(0.8,0.5)
  rect 0.5x1.26 smd: 7(0,0)
  silkscreen extent -1.2,-1.35 0.83,1.35, body extent -0.83,-0.82 0.83,0.82, height 0.6
QFN50P400X400X80_HS-21N [mm] "QFN, 20-Leads, Body 4.00x4.00mm, Pitch 0.50mm, Thermal Pad 2.10x2.10mm, IPC Medium Density"
  oval 0.95x0.25 smd: 1(-1.925,1) 2(-1.925,0.5) 3(-1.925,0) 4(-1.925,-0.5) 5(-1.925,-1) 11(1.925,-1) 12(1.925,-0.5) 13(1.925,0) 14(1.925,0.5) 15(1.925,1)
  oval 0.25x0.95 smd: 6(-1,-1.925) 7(-0.5,-1.925) 8(0,-1.925) 9(0.5,-1.925) 10(1,-1.925) 16(1,1.925) 17(0.5,1.925) 18(0,1.925) 19(-0.5,1.925) 20(-1,1.925)
  rect 2.1x2.1 smd: 21(0,0)
  silkscreen extent -2.97,-2.2 2.2,2.2, body extent -2,-2 2,2, height 0.92
RESC1005X04L [mm] "Chip Resistor, 2-Leads, Body 1.0x0.5mm, IPC High Density"
  rect 0.6x0.55 smd: 1(-0.5,0) 2(0.5,0)
  silkscreen extent -0.87,-0.38 0.88,0.38, body extent -0.5,-0.25 0.5,0.25, height 0.3
SOCKET_1x6_SMD [mm] "Socket, 2.54mm, SMD"
  rect 1.02x2.19 smd: 1(0,-1.465) 1(0,1.465) 2(2.54,-1.465) 2(2.54,1.465) 3(5.08,-1.465) 3(5.08,1.465) 4(7.62,-1.465) 4(7.62,1.465) 5(10.16,-1.465) 5(10.16,1.465) 6(12.7,1.465) 6(12.7,-1.465)
  silkscreen extent -1.27,-1.27 13.97,1.27
SOCKET_1x8_SMD [mm] "Socket, 2.54mm, SMD"
  rect 1.02x2.19 smd: 1(0,-1.465) 1(0,1.465) 2(2.54,-1.465) 2(2.54,1.465) 3(5.08,-1.465) 3(5.08,1.465) 4(7.62,-1.465) 4(7.62,1.465) 5(10.16,-1.465) 5(10.16,1.465) 6(12.7,1.465) 6(12.7,-1.465) 7(15.24,-1.465) 7(15.24,1.465) 8(17.78,-1.465) 8(17.78,1.465)
  silkscreen extent -1.27,-1.27 19.05,1.27
SOCKET_1x9_SMD [mm] "Socket, 2.54mm, SMD"
  rect 1.02x2.19 smd: 1(0,1.465) 1(0,-1.465) 2(2.54,-1.465) 2(2.54,1.465) 3(5.08,-1.465) 3(5.08,1.465) 4(7.62,-1.465) 4(7.62,1.465) 5(10.16,-1.465) 5(10.16,1.465) 6(12.7,1.465) 6(12.7,-1.465) 7(15.24,-1.465) 7(15.24,1.465) 8(17.78,-1.465) 8(17.78,1.465) 9(20.32,-1.465) 9(20.32,1.465)
  silkscreen extent -1.27,-1.27 21.59,1.27
SOCKET_1x10_SMD [mm] "Socket, 2.54mm, SMD"
  rect 1.02x2.19 smd: 1(0,1.465) 1(0,-1.465) 2(2.54,-1.465) 2(2.54,1.465) 3(5.08,-1.465) 3(5.08,1.465) 4(7.62,-1.465) 4(7.62,1.465) 5(10.16,-1.465) 5(10.16,1.465) 6(12.7,-1.465) 6(12.7,1.465) 7(15.24,-1.465) 7(15.24,1.465) 8(17.78,-1.465) 8(17.78,1.465) 9(20.32,-1.465) 9(20.32,1.465) 10(22.86,-1.465) 10(22.86,1.465)
  silkscreen extent -1.27,-1.27 24.13,1.27
SOCKET_2x3_SMD-2.54mm-bottom [mm] "Socket, 2.54mm, SMD"
  rect 1.02x2.22 smd far side: 1(-2.54,-2.825) 2(-2.54,2.825) 3(0,-2.825) 4(0,2.825) 5(2.54,-2.825) 6(2.54,2.825)
SOD-523 [mm] "SOT-363 (SC88)"
  rect 0.4x0.5 smd: 1(0.7,0) 3(-0.7,0)
  silkscreen extent -0.6,-0.4 0.6,0.4, body extent -0.8,-0.4 0.8,0.4, height 0.7
Solderbridge#1 [mm]
  round 0.2 smd paste-10: 1(0,0) 2(0.625,0)
  Top Layer region: 0.236,-0.432 0.16,-0.505 0.042,-0.467 -0.023,-0.424 -0.097,-0.351 -0.15,-0.292 -0.208,-0.193 -0.236,-0.099 -0.231,0.122 -0.206,0.193 -0.122,0.33 -0.038,0.411 0.054,0.469 0.155,0.5 0.206,0.483 0.236,0.43
  Top Layer region: 0.389,0.432 0.465,0.505 0.583,0.467 0.648,0.424 0.721,0.351 0.775,0.292 0.833,0.193 0.861,0.099 0.856,-0.122 0.831,-0.193 0.747,-0.33 0.663,-0.411 0.571,-0.469 0.47,-0.5 0.419,-0.483 0.389,-0.43
  Top Layer lines w0.152: 0.465,0.431 cw(c0.355,0) 0.465,-0.431 ; 0.159,0.431 ccw(c0.27,0) 0.159,-0.431
Solderbridge#2 [mm]
  round 0.2 smd paste-10: 1(0,0) 2(0.625,0)
  Top Layer region: 0.236,-0.432 0.16,-0.505 0.042,-0.467 -0.023,-0.424 -0.097,-0.351 -0.15,-0.292 -0.208,-0.193 -0.236,-0.099 -0.231,0.122 -0.206,0.193 -0.122,0.33 -0.038,0.411 0.054,0.469 0.155,0.5 0.206,0.483 0.236,0.43
  Top Layer region: 0.389,0.432 0.465,0.505 0.583,0.467 0.648,0.424 0.721,0.351 0.775,0.292 0.833,0.193 0.861,0.099 0.856,-0.122 0.831,-0.193 0.747,-0.33 0.663,-0.411 0.571,-0.469 0.47,-0.5 0.419,-0.483 0.389,-0.43
  Top Layer lines w0.152: 0.465,0.431 cw(c0.355,0) 0.676,0.308 cw(c0.355,0) 0.774,0.149 cw(c0.355,0) 0.465,-0.431 ; 0.159,0.431 ccw(c0.27,0) -0.175,0 ccw(c0.27,0) -0.153,-0.138 ccw(c0.27,0) -0.108,-0.235 ccw(c0.27,0) 0.159,-0.431
Solderbridge_Shorted [mm]
  round 0.2 smd paste-10: 1(0,0) 2(0.676,0)
  Top Layer region: 0.236,-0.432 0.16,-0.505 0.042,-0.467 -0.023,-0.424 -0.097,-0.351 -0.15,-0.292 -0.208,-0.193 -0.236,-0.099 -0.231,0.122 -0.206,0.193 -0.122,0.33 -0.038,0.411 0.054,0.469 0.155,0.5 0.206,0.483 0.236,0.43
  Top Layer region: 0.44,0.432 0.516,0.505 0.634,0.467 0.699,0.424 0.772,0.351 0.826,0.292 0.884,0.193 0.912,0.099 0.907,-0.122 0.881,-0.193 0.798,-0.33 0.714,-0.411 0.622,-0.469 0.521,-0.5 0.47,-0.483 0.44,-0.43
  Top Layer lines w0.152: 0.159,-0.431 cw(c0.27,0) 0.159,0.431 ; 0.516,-0.431 ccw(c0.406,0) 0.516,0.431
  Top Layer lines w0.203: 0,0 0.676,0
SOT65P210X110-3N [mm] "SOT323 (SC-70), 3-Leads, Body 2,00x2,10mm, Pitch 0,65mm, IPC Medium Density"
  rect 1.3x0.55 smd: 1(-0.85,0.65) 2(-0.85,-0.65) 3(0.85,0)
  silkscreen extent -0.97,-1.1 0.67,1.6, body extent -1.15,-1.05 1.15,1.05, height 1
SOT95P280X145-5N [mm] "SOT23, 5-Leads, Body 3,1x3,0mm (max), Pitch 0,95mm, IPC Medium Density"
  rect 1.1x0.6 smd: 1(-1.2,0.95) 2(-1.2,0) 3(-1.2,-0.95) 4(1.2,-0.95) 5(1.2,0.95)
  silkscreen extent -1.33,-1.55 0.25,1.92, body extent -1.5,-1.5 1.5,1.5, height 1.45
SOT95P280X145-6N [mm] "SOT23, 6-Leads, Body 3,1x3,0mm (max), Pitch 0,95mm, IPC Medium Density"
  rect 1.1x0.6 smd: 1(-1.2,0.95) 2(-1.2,0) 3(-1.2,-0.95) 4(1.2,-0.95) 5(1.2,0) 6(1.2,0.95)
  silkscreen extent -1.32,-1.55 0.25,1.92, body extent -1.5,-1.5 1.5,1.5, height 1.45
SOT-23-5 [mm] "SOT-23/SC-74A; 5 Leads; Body 3.1 x 3 mm, inc. leads (LxW max)"
  rect 0.55x1.45 smd: 1(-0.95,-1.075) 2(0,-1.075) 3(0.95,-1.075) 4(0.95,1.075) 5(-0.95,1.075)
  silkscreen extent -1.57,-1.35 1.55,0.9, body extent -1.5,-1.5 1.5,1.5, height 1.3
SOT-353 [mm]
  rect 0.4x0.7 smd: 1(0,0) 2(0.65,0) 3(1.3,0) 4(1.3,2) 5(0,2)
  silkscreen extent -0.45,0.2 1.75,1.8
SOT-363 [mm] "SOT-363 (SC88)"
  rect 0.3x0.7 smd: 1(0,0) 2(0.65,0) 3(1.3,0) 4(1.3,1.6) 5(0.65,1.6) 6(0,1.6)
  silkscreen extent -0.83,-0.27 1.65,1.4, body extent -0.35,-0.25 1.65,1.85, height 0.93
TEST_POINT_5000 [mm] "KEYSTONE 5000 MINIATURE RED - THRU HOLE MOUNT TEST POINT"
  round 1.5 hole 1: 1(0,0)
  silkscreen extent -1.25,-1.25 1.25,1.25
TEST_POINT_5001 [mm] "KEYSTONE 5001 MINIATURE BLACK - THRU HOLE MOUNT TEST POINT"
  round 1.5 hole 1: 1(0,0)
  silkscreen extent -1.25,-1.25 1.25,1.25
TP_SMD_Ø1.5mm [mm]
  round 1.5 smd paste-5: 1(0,0)
  silkscreen extent -0.95,-0.95 0.95,0.95
TP_SMD_Ø1.5MM [mm]
  round 1.5 smd paste-5: 1(0,0)
  silkscreen extent -0.95,-0.95 0.95,0.95
TSOP65P640X120-8N [mm] "TSOP, 8-Leads, Body 3.00x4.40mm, Pitch 0.65mm, IPC Medium Density"
  oval 1.4x0.45 smd: 1(-2.95,0.975) 2(-2.95,0.325) 3(-2.95,-0.325) 4(-2.95,-0.975) 5(2.95,-0.975) 6(2.95,-0.325) 7(2.95,0.325) 8(2.95,0.975)
  silkscreen extent -3.08,-1.55 1.85,1.87, body extent -3.2,-1.55 3.2,1.55, height 1.2
USB-Micro-B-RA-SMD-PiP [mm] "Micro USB B SMT"
  rect 1.35x0.4 smd: 1(0,1.3) 2(0,0.65) 3(0,0) 4(0,-0.65) 5(0,-1.3)
  oval 1.6x0.9 hole 0.5 slot 1.2 at 0 deg: 6(-2.675,-3.3) 6(-2.675,3.3)
  oval 2x1.5 on Top Paste: 6(-2.675,-3.3) 6(-2.675,3.3)
  rect 1.55x1.9 smd: 6(-2.675,-1.2) 6(-2.675,1.2)
  rect 1.4x1.6 smd: 6(-0.225,-3.2) 6(-0.225,3.2)
  silkscreen extent -4.75,-3.75 0.25,3.75, body extent -5.28,-4.1 0.15,4.1, height 2.72
WE-TPC_4848 [mm] "Inductor SMD"
  rect 4x0.5 smd: 1(0,2.3) 2(0,-2.3)
  Top Layer region: 2.65,0.75 2.65,2.75 -2.65,2.75 -2.65,0.75 -1.635,0.75 -1.545,0.934 -1.431,1.093 -1.17,1.354 -0.83,1.599 -0.447,1.758 -0.222,1.81 0.01,1.824 0.353,1.784 0.664,1.688 1.094,1.44 1.484,1.049 1.637,0.75
  Top Layer region: -2.65,-0.75 -2.65,-2.75 2.65,-2.75 2.65,-0.75 1.635,-0.75 1.545,-0.934 1.431,-1.093 1.17,-1.354 0.83,-1.599 0.447,-1.758 0.222,-1.81 -0.01,-1.824 -0.353,-1.784 -0.664,-1.688 -1.094,-1.44 -1.484,-1.049 -1.637,-0.75
  silkscreen extent -2.65,-2.4 2.65,2.4, body extent -2.4,-2.4 2.4,2.4, height 2.8

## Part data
A1: library part "Johanson 2450AT18D0100_STD", "2.45 GHz chip antenna"
C1 C2: library part C0402-12p, "Capacitor, NP0, ±2%"
C3: library part C0402-0.8p, "Capacitor, NP0, ±5%"
C4 C5 C8 C11 C12 C13 C16 C17 C23 C24 C30 C32 C33 C36 C37 C41 C42 C45 C46 C47 C48 C49 C50 C51 C52 C53 C54 C55 C56 C57 C60 C64 C66: library part C0402-100n, "Capacitor, X7R, ±10%"
C6 C14 C15: library part C0402-N.C., "Not mounted"
C7: library part C0402-100p, "Capacitor, NP0, ±5%"
C9: library part C0603-4µ7, "Capacitor, X5R, ±10%"
C10: library part C0603-1µ0, "Capacitor, X7R, ±10%"
C18 C19 C20 C21 C22 C29 C58 C59 C65 C67: library part C0402-1µ0, "Capacitor, X5R, ±5%"
C25 C27: library part C0402-2.2p, "Capacitor, NP0, ±0.1pF"
C26: library part C0402-220p, "Chip Cap 0402"
C28: library part C0402-4µ7, "Chip Cap 0402"
C31 C35 C40 C44: library part C0402-2µ2, "Chip Cap 0402"
C34 C43: library part C0402-1n0, "Capacitor, X7R, ±10%"
C38 C39: library part C1206-47µ_Tantal, "Capacitor, Tantalum, ±10%"
C61 C62: library part C3528-330µF, "Capacitor, Tantalum, ±20%, 3528"
C63: library part C0603-10µ, "Capacitor, X5R, ±20%"
D1 D7: "Surface Mount Schottky Barrier Diode Array"
D2 D3 D4 D5 D6: "Diode Schottky Vf=0.38, Vr=40V, If=200mA, Ir=500nA"
FB1 FB2: library part FB0603-1k@100MHz-800mA, "Ferrite Bead, 1 kOhm @ 100MHz, 800mA, 300 mOhm Max"
Fid1 Fid2: library part Fid-Mark, "Fiducial Mark"
J1: library part USB-Micro-B-RA-SMD-PiP, "MicroUSB-B-SMT"
L1: library part L0402-3n9, "Inductor, 170mA, ±0.1nH"
L2: library part L4848-220µH, "FIXED IND 470UH 240MA 2.6 OHM"
LED1 LED2: library part EL19-21SYGC, "LED 0603, EL19-21SYGC"
LOGO1: "Nordic Logo, medium size"
P1 P8: library part "Pin List 1x8 SMD", "Pin List 1x8, 2.54mm (100mil), SMD"
P2 P3 P9 P10 P19: library part "Socket 1x8 SMD", "Socket 1x8, 2.54mm (100mil), SMD"
P4: library part "Pin List 1x6 SMD", "Pin List 1x6, 2.54mm (100mil), SMD"
P5 P6: library part "Socket 1x6 SMD", "Socket 1x6, 2.54mm (100mil), SMD"
P7: "Pin List 1x2, 2.54mm (100mil)"
P11: library part "Pin List 1x10 SMD", "Pin List 1x10, 2.54mm (100mil), SMD"
P12 P13: library part "Socket 1x10 SMD", "Socket 1x10, 2.54mm (100mil), SMD"
P14: library part "Socket 2x3 SMD Bottom", "Socket 2x3, 2.54mm (100mil), SMD"
P15: library part "Pin Header 2x3 SMD", "Pin Header 2x3, 2.54mm (100mil) SMD"
P16 P22: library part "Pin List Ang 1x2 SMD, 2.54mm", "Pin List 1x2, 2.54mm (100mil), Right Angled, SMD"
P17: library part "Pin List 1x9 SMD", "Pin List 1x9, 2.54mm (100mil), SMD"
P18: library part "Socket 1x9 SMD", "Socket 1x9, 2.54mm (100mil), SMD"
P20: library part "Pin List Ang 1x3 SMD, 2.54mm", "Pin List 1x3, 2.54mm (100mil), Right Angled, SMD"
P21: library part "Pin Header 2x5 SMD, 1.27mm, KS", "Pin Header 2x5, 1.27mm (50mil), SMD, Keying Shroud"
Q1 Q2: library part DMMT3904W-7-F, "40V Matched pair NPN Small signal transistor"
Q3 Q4: library part BSS138PW, "60 V, 320 mA N-channel Trench MOSFET"
R1 R5 R6 R11: library part R0402-47k, "Resistor, ±1%, 0.063W"
R2: library part R0402-510_0.1%, "Resistor, ±0.1%, 0.063W"
R3: library part R0402-33R_0.1%, "Resistor, ±0.1%, 0.063W"
R4: library part R0402-1R8, "Resistor, ±1%, 0.063W"
R7: library part R0402-0R, "Resistor, ±5%, 0.063W"
R8 R9: library part R0402-4k7, "Resistor, ±1%, 0.063W"
R10 R12: library part R0402-220, "Resistor, ±1%, 0.063W"
R13 R14 R15 R16 R17: library part R0402-100k, "Resistor, ±1%, 0.063W"
R18 R19 R20 R21 R22: library part R0402-18k, "Resistor, ±1%, 0.063W"
R23: library part R0402-1k0_0.1%, "Resistor, ±0.1%, 0.063W"
R24: library part R0402-100_0.1%, "Resistor, ±0.1%, 0.063W"
R25: library part R0402-10R, "Resistor, ±1%, 0.063W"
R26: library part R0402-10k_0.1%, "Resistor, ±0.1%, 0.063W"
R27 R28 R29 R31 R34 R35 R37 R38 R49: library part R0402-10k, "Resistor, ±1%, 0.063W"
R30 R39 R41 R42 R43 R45 R46 R50: library part R0402-1k0, "Resistor, ±1%, 0.063W"
R32: library part R0402-27k, "Resistor, ±1%, 0.063W"
R33: library part R0402-30k, "Resistor, ±1%, 0.063W"
R36: library part R0402-2k0, "Resistor, ±1%, 0.063W"
R40 R44: library part R0402-100, "Resistor, ±1%, 0.063W"
R47: library part R0402-62k, "Resistor, ±1%, 0.063W"
R48: library part R0402-33k, "Resistor, ±1%, 0.063W"
SB1 SB2 SB7: library part "Solderbridge Shorted", "Shorted Solderbridge"
SW1: library part ALPS_SKRHAAE010, "ALPS - SKRHAAE010, Multi-directional Switches 4-directn cntr push w/o boss 200K cycles, SMD, 7.5x7.5x5mm"
SW2: "Slide Switch DPDT 200mA 12V"
SW3: library part CJS-1200TA, "SMD slide Switch (ON-ON)"
SW4: "Low-profile slide switch, SP3T, ON-ON-ON"
TP1 TP2 TP3 TP4 TP6 TP7 TP8 TP12 TP13 TP14 TP15 TP16 TP17 TP18 TP19 TP20 TP21: library part TP_SMD_Ø1.5MM, "1.0mm circular SMD testpad"
TP5: library part "TP - Keystone 5000", "Miniature THM Test Point -Red P/N 5000"
TP9 TP10: library part "TP - Keystone 5001", "Miniature THM Test Point -Black P/N 5001"
TP11: library part TP_SMD_Ø1.0MM, "1.0mm circular SMD testpad"
U1: "Multi-protocol Bluetooth Low Energy and 2.4GHz proprietary system-on-chip"
U2 U3 U4: "SWITCH SPST SOT23-6"
U5: "Quad Digital Potentiometer, 100k, 257 taps, I2C interface, Volatile Memory, 1.8-5.5V"
U6: library part M24C02-FDW6TP, "2-Kbit serial I²C bus EEPROM"
U7 U9: library part TLV272CM8-13, "Dual rail to rail CMOS Amplifier"
U8: library part AD8615AUJZ-REEL7, "IC OPAMP GP 24MHZ RRO TSOT23-5"
U10: "300 mA, Low Voltage, Low Quiescent Current LDO Regulator"
U11 U12 U13 U14: "IC 2.9ns COMPARATOR, Rail-to-Rail input CMOS output, MSOP-8"
U15 U20 U21: "Unbuffered Inverter"
U16 U19 U24: library part 74LVC2G08GF, "IC DUAL 2IN POS-AND GATE SOT-1089"
U17 U18 U22 U23: library part 74LVC1G17SE, "Single schmitt-trigger buffer with standard push-pull output"
U25: library part MIC5353YMT, "500mA LDO adjustable"
X1: library part XTAL_SMD2016_32MHz_8pF_Kyocera, "XTAL SMD 2016, 32MHz, Cl=8pF, Tot: ±40ppm"

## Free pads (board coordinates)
  oval 450x300 hole 300 slot 450 at 0 deg unplated: 1(3241.48,1607.09)
  round 126 hole 126: 063_070(550,125) 064_089(600,2025) 084_072(2600,325) 084_083(2600,1425) 093_089(3582.68,2241.54)

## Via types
v1: diameter 24, hole 12, Top Layer to Bottom Layer, tented both sides, 666 vias
v2: diameter 23.62, hole 11.81, Top Layer to Bottom Layer, tented both sides, 68 vias
v3: diameter 25.98, hole 12.99, Top Layer to Bottom Layer, tented both sides, 16 vias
